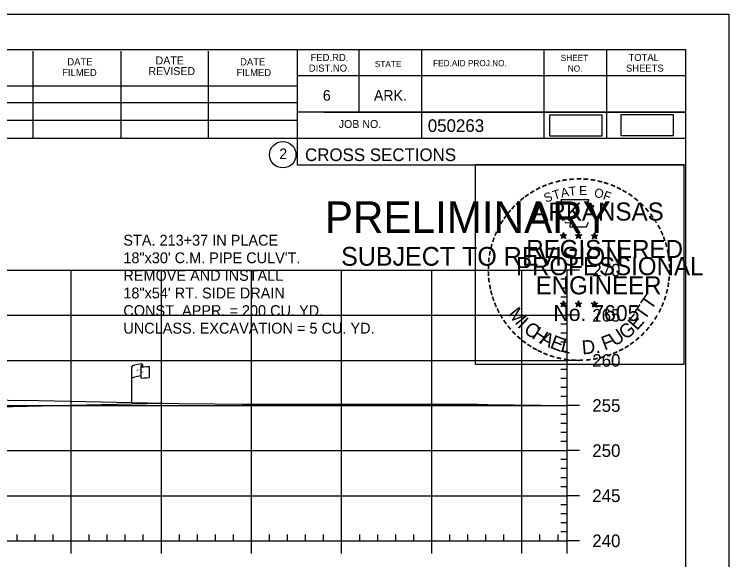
# Model space of a CAD drawing. Extents: x 1365647 to 1367999, y 387113 to 400173.
# Drawn here: x 1365977.8 to 1366057, y 390725.7 to 390786.1 of the extents above; entities that cross this region are included whole.
import ezdxf

# ---------------------------------------------------------------- set-up
doc = ezdxf.new("R2010")
doc.units = 0
for name, color, linetype in [('E_Existing ROW', 7, 'Continuous'), ('R_Axis', 7, 'Continuous'), ('R_Axis Annot', 7, 'Continuous'), ('R_Border', 7, 'Continuous'), ('R_Border PE', 7, 'Continuous'), ('R_Border Prem', 7, 'Continuous'), ('R_Detour', 7, 'Continuous'), ('R_Draft', 7, 'Continuous'), ('R_Drive', 7, 'Continuous'), ('R_Exist Surface', 7, 'Continuous'), ('R_Grid', 7, 'Continuous'), ('R_No Plot', 7, 'Continuous')]:
    doc.layers.add(name, color=color, linetype=linetype)

msp = doc.modelspace()

# ---------------------------------------------------------------- linework, layer by layer
at = {"layer": 'E_Existing ROW'}
for p, q in [((1365991.992, 390747.314), (1365991.992, 390747.074)), ((1365990.829, 390743.113), (1365990.829, 390747.064)), ((1365991.824, 390747.158), (1365991.824, 390747.145)), ((1365991.824, 390747.145), (1365991.824, 390745.918)), ((1365992.76, 390747.121), (1365992.76, 390745.881))]:
    msp.add_line(p, q, dxfattribs=at)
for centre, radius, start, end in [((1365991.902, 390747.159), 0.078, 88.6458, 274.28284), ((1365991.914, 390747.314), 0.0783, 263.07118, 93.95638), ((1365991.903, 390745.918), 0.0783, 180, 273.95638)]:
    msp.add_arc(centre, radius, start, end, dxfattribs=at)
for centre, major_axis, ratio, start_param, end_param in [((1365992.411, 390747.107), (-1.582, -0.043), 0.19887, 5.030368, 6.283185), ((1365993.118, 390747.223), (-1.227, -0.134), 0.052933, 0.159456, 1.268315), ((1365992.406, 390745.789), (-1.582, -0.043), 0.19887, 5.083035, 6.194897), ((1365993.118, 390745.982), (-1.227, -0.134), 0.052933, 0.159456, 1.268315)]:
    msp.add_ellipse(centre, major_axis=major_axis, ratio=ratio, start_param=start_param, end_param=end_param, dxfattribs=at)
at = {"layer": 'R_Axis'}
for p, q in [((1366039.095, 390727.787), (1366039.095, 390757.787)), ((1366040.495, 390757.787), (1366039.095, 390757.787)), ((1366039.095, 390756.787), (1366038.395, 390756.787)), ((1366039.095, 390755.787), (1366038.395, 390755.787)), ((1366039.095, 390754.787), (1366038.395, 390754.787)), ((1366039.095, 390753.787), (1366038.395, 390753.787)), ((1366040.495, 390752.787), (1366039.095, 390752.787)), ((1366039.095, 390751.787), (1366038.395, 390751.787)), ((1366039.095, 390750.787), (1366038.395, 390750.787)), ((1366039.095, 390749.787), (1366038.395, 390749.787)), ((1366039.095, 390748.787), (1366038.395, 390748.787)), ((1366040.495, 390747.787), (1366039.095, 390747.787)), ((1366039.095, 390746.787), (1366038.395, 390746.787)), ((1366039.095, 390745.787), (1366038.395, 390745.787)), ((1366039.095, 390744.787), (1366038.395, 390744.787)), ((1366039.095, 390743.787), (1366038.395, 390743.787)), ((1366040.495, 390742.787), (1366039.095, 390742.787)), ((1366039.095, 390741.787), (1366038.395, 390741.787)), ((1366039.095, 390740.787), (1366038.395, 390740.787)), ((1366039.095, 390739.787), (1366038.395, 390739.787)), ((1366039.095, 390738.787), (1366038.395, 390738.787)), ((1366040.495, 390737.787), (1366039.095, 390737.787)), ((1366039.095, 390736.787), (1366038.395, 390736.787)), ((1366039.095, 390735.787), (1366038.395, 390735.787)), ((1366039.095, 390734.787), (1366038.395, 390734.787)), ((1366039.095, 390733.787), (1366038.395, 390733.787)), ((1366040.495, 390732.787), (1366039.095, 390732.787)), ((1366039.095, 390731.787), (1366038.395, 390731.787)), ((1366039.095, 390730.787), (1366038.395, 390730.787)), ((1366039.095, 390729.787), (1366038.395, 390729.787)), ((1365978.095, 390727.787), (1365978.095, 390728.487)), ((1365980.095, 390727.787), (1365980.095, 390728.487)), ((1365982.095, 390727.787), (1365982.095, 390728.487)), ((1365986.095, 390727.787), (1365986.095, 390728.487)), ((1365988.095, 390727.787), (1365988.095, 390728.487)), ((1365990.095, 390727.787), (1365990.095, 390728.487)), ((1365992.095, 390727.787), (1365992.095, 390728.487)), ((1365996.095, 390727.787), (1365996.095, 390728.487)), ((1365998.095, 390727.787), (1365998.095, 390728.487)), ((1366000.095, 390727.787), (1366000.095, 390728.487)), ((1366002.095, 390727.787), (1366002.095, 390728.487)), ((1366006.095, 390727.787), (1366006.095, 390728.487)), ((1366008.095, 390727.787), (1366008.095, 390728.487)), ((1366010.095, 390727.787), (1366010.095, 390728.487)), ((1366012.095, 390727.787), (1366012.095, 390728.487)), ((1366016.095, 390727.787), (1366016.095, 390728.487)), ((1366018.095, 390727.787), (1366018.095, 390728.487)), ((1366020.095, 390727.787), (1366020.095, 390728.487)), ((1366022.095, 390727.787), (1366022.095, 390728.487)), ((1366026.095, 390727.787), (1366026.095, 390728.487)), ((1366028.095, 390727.787), (1366028.095, 390728.487)), ((1366030.095, 390727.787), (1366030.095, 390728.487)), ((1366032.095, 390727.787), (1366032.095, 390728.487)), ((1366036.095, 390727.787), (1366036.095, 390728.487)), ((1366038.095, 390727.787), (1366038.095, 390728.487)), ((1366039.095, 390728.787), (1366038.395, 390728.787)), ((1365749.095, 390727.787), (1366039.095, 390727.787)), ((1365984.095, 390726.387), (1365984.095, 390727.787)), ((1365994.095, 390726.387), (1365994.095, 390727.787)), ((1366004.095, 390726.387), (1366004.095, 390727.787)), ((1366014.095, 390726.387), (1366014.095, 390727.787)), ((1366024.095, 390726.387), (1366024.095, 390727.787)), ((1366034.095, 390726.387), (1366034.095, 390727.787)), ((1366039.095, 390726.387), (1366039.095, 390727.787)), ((1366040.495, 390727.787), (1366039.095, 390727.787))]:
    msp.add_line(p, q, dxfattribs=at)
at = {"layer": 'R_Border'}
for p, q in [((1365736.095, 390782.247), (1366052.275, 390782.247)), ((1366009.175, 390782.247), (1366009.175, 390769.447)), ((1366016.015, 390782.247), (1366016.015, 390775.307)), ((1366022.955, 390782.247), (1366022.955, 390772.367)), ((1366036.535, 390782.247), (1366036.535, 390772.367)), ((1366043.475, 390782.247), (1366043.475, 390772.367)), ((1366052.275, 390576.787), (1366052.275, 390782.247)), ((1365979.875, 390772.367), (1365979.875, 390782.047)), ((1365989.635, 390772.367), (1365989.635, 390782.047)), ((1365999.315, 390772.367), (1365999.315, 390782.047)), ((1366052.275, 390779.307), (1366009.175, 390779.307)), ((1366052.275, 390779.327), (1366052.275, 390779.327)), ((1365970.015, 390778.227), (1366009.175, 390778.227)), ((1365970.015, 390776.367), (1366009.175, 390776.367)), ((1366052.275, 390775.307), (1366009.175, 390775.307)), ((1366012.135, 390775.307), (1366052.275, 390775.307)), ((1365970.015, 390774.427), (1366009.175, 390774.427)), ((1366052.275, 390772.367), (1365970.015, 390772.367)), ((1366009.175, 390769.447), (1366052.275, 390769.447))]:
    msp.add_line(p, q, dxfattribs=at)
msp.add_circle((1366007.562, 390770.582), 1.467, dxfattribs=at)
at = {"layer": 'R_Border PE'}
for p, q in [((1366038.356, 390761.693), (1366038.705, 390761.582)), ((1366038.356, 390761.693), (1366038.609, 390761.648)), ((1366038.356, 390761.693), (1366038.593, 390761.571)), ((1366038.489, 390761.285), (1366038.705, 390761.582)), ((1366038.489, 390761.285), (1366038.615, 390761.529)), ((1366038.489, 390761.285), (1366038.703, 390761.502)), ((1366038.705, 390761.947), (1366038.664, 390761.695)), ((1366038.918, 390761.285), (1366038.703, 390761.499)), ((1366038.705, 390761.582), (1366038.705, 390761.947)), ((1366038.705, 390761.947), (1366038.754, 390761.697)), ((1366039.052, 390761.693), (1366038.705, 390761.582)), ((1366038.918, 390761.285), (1366038.705, 390761.582)), ((1366039.052, 390761.693), (1366038.766, 390761.644)), ((1366038.918, 390761.285), (1366038.781, 390761.576)), ((1366039.052, 390761.693), (1366038.848, 390761.591)), ((1366040.026, 390761.693), (1366040.375, 390761.582)), ((1366040.026, 390761.693), (1366040.279, 390761.648)), ((1366040.026, 390761.693), (1366040.263, 390761.571)), ((1366040.159, 390761.285), (1366040.375, 390761.582)), ((1366040.159, 390761.285), (1366040.285, 390761.529)), ((1366040.159, 390761.285), (1366040.373, 390761.502)), ((1366040.375, 390761.947), (1366040.334, 390761.695)), ((1366040.588, 390761.285), (1366040.373, 390761.499)), ((1366040.375, 390761.582), (1366040.375, 390761.947)), ((1366040.375, 390761.947), (1366040.424, 390761.697)), ((1366040.722, 390761.693), (1366040.375, 390761.582)), ((1366040.588, 390761.285), (1366040.375, 390761.582)), ((1366040.722, 390761.693), (1366040.436, 390761.644)), ((1366040.588, 390761.285), (1366040.451, 390761.576)), ((1366040.722, 390761.693), (1366040.518, 390761.591)), ((1366041.79, 390761.681), (1366042.139, 390761.57)), ((1366041.79, 390761.681), (1366042.043, 390761.636)), ((1366041.79, 390761.681), (1366042.027, 390761.559)), ((1366041.923, 390761.273), (1366042.139, 390761.57)), ((1366041.923, 390761.273), (1366042.049, 390761.517)), ((1366041.923, 390761.273), (1366042.137, 390761.49)), ((1366042.139, 390761.935), (1366042.098, 390761.683)), ((1366042.352, 390761.273), (1366042.137, 390761.487)), ((1366042.139, 390761.57), (1366042.139, 390761.935)), ((1366042.139, 390761.935), (1366042.188, 390761.685)), ((1366042.486, 390761.681), (1366042.139, 390761.57)), ((1366042.352, 390761.273), (1366042.139, 390761.57)), ((1366042.486, 390761.681), (1366042.2, 390761.632)), ((1366042.352, 390761.273), (1366042.215, 390761.564)), ((1366042.486, 390761.681), (1366042.282, 390761.579)), ((1366038.701, 390754.374), (1366038.66, 390754.122)), ((1366038.701, 390754.009), (1366038.701, 390754.374)), ((1366038.701, 390754.374), (1366038.75, 390754.124)), ((1366040.37, 390754.374), (1366040.329, 390754.122)), ((1366040.37, 390754.009), (1366040.37, 390754.374)), ((1366040.37, 390754.374), (1366040.419, 390754.124)), ((1366042.137, 390754.364), (1366042.096, 390754.112)), ((1366042.137, 390753.999), (1366042.137, 390754.364)), ((1366042.137, 390754.364), (1366042.186, 390754.114)), ((1366038.352, 390754.12), (1366038.701, 390754.009)), ((1366038.352, 390754.12), (1366038.605, 390754.075)), ((1366038.352, 390754.12), (1366038.589, 390753.998)), ((1366038.485, 390753.712), (1366038.701, 390754.009)), ((1366038.485, 390753.712), (1366038.611, 390753.956)), ((1366038.485, 390753.712), (1366038.699, 390753.929)), ((1366038.914, 390753.712), (1366038.699, 390753.926)), ((1366039.048, 390754.12), (1366038.701, 390754.009)), ((1366038.914, 390753.712), (1366038.701, 390754.009)), ((1366039.048, 390754.12), (1366038.762, 390754.071)), ((1366038.914, 390753.712), (1366038.777, 390754.003)), ((1366039.048, 390754.12), (1366038.844, 390754.018)), ((1366040.021, 390754.12), (1366040.37, 390754.009)), ((1366040.021, 390754.12), (1366040.274, 390754.075)), ((1366040.021, 390754.12), (1366040.258, 390753.998)), ((1366040.154, 390753.712), (1366040.37, 390754.009)), ((1366040.154, 390753.712), (1366040.28, 390753.956)), ((1366040.154, 390753.712), (1366040.368, 390753.929)), ((1366040.583, 390753.712), (1366040.368, 390753.926)), ((1366040.717, 390754.12), (1366040.37, 390754.009)), ((1366040.583, 390753.712), (1366040.37, 390754.009)), ((1366040.717, 390754.12), (1366040.431, 390754.071)), ((1366040.583, 390753.712), (1366040.446, 390754.003)), ((1366040.717, 390754.12), (1366040.513, 390754.018)), ((1366041.788, 390754.11), (1366042.137, 390753.999)), ((1366041.788, 390754.11), (1366042.041, 390754.065)), ((1366041.788, 390754.11), (1366042.025, 390753.988)), ((1366041.921, 390753.702), (1366042.137, 390753.999)), ((1366041.921, 390753.702), (1366042.047, 390753.946)), ((1366041.921, 390753.702), (1366042.135, 390753.919)), ((1366042.35, 390753.702), (1366042.135, 390753.916)), ((1366042.484, 390754.11), (1366042.137, 390753.999)), ((1366042.35, 390753.702), (1366042.137, 390753.999)), ((1366042.484, 390754.11), (1366042.198, 390754.061)), ((1366042.35, 390753.702), (1366042.213, 390753.993)), ((1366042.484, 390754.11), (1366042.28, 390754.008))]:
    msp.add_line(p, q, dxfattribs=at)
for points in [[(1366038.397, 390765.571), (1366038.666, 390764.744)], [(1366041.908, 390764.649), (1366042.05, 390764.933), (1366041.365, 390764.909), (1366041.513, 390765.571), (1366038.397, 390765.571)], [(1366038.889, 390763.148), (1366038.889, 390763.061), (1366039.452, 390763.042), (1366039.398, 390762.569), (1366041.268, 390762.569), (1366041.469, 390763.105)], [(1366038.705, 390761.947), (1366038.918, 390761.285), (1366038.356, 390761.693), (1366039.052, 390761.693), (1366038.489, 390761.285), (1366038.705, 390761.947)], [(1366040.375, 390761.947), (1366040.588, 390761.285), (1366040.026, 390761.693), (1366040.722, 390761.693), (1366040.159, 390761.285), (1366040.375, 390761.947)], [(1366042.139, 390761.935), (1366042.352, 390761.273), (1366041.79, 390761.681), (1366042.486, 390761.681), (1366041.923, 390761.273), (1366042.139, 390761.935)], [(1366038.701, 390754.374), (1366038.914, 390753.712), (1366038.352, 390754.12), (1366039.048, 390754.12), (1366038.485, 390753.712), (1366038.701, 390754.374)], [(1366040.37, 390754.374), (1366040.583, 390753.712), (1366040.021, 390754.12), (1366040.717, 390754.12), (1366040.154, 390753.712), (1366040.37, 390754.374)], [(1366042.137, 390754.364), (1366042.35, 390753.702), (1366041.788, 390754.11), (1366042.484, 390754.11), (1366041.921, 390753.702), (1366042.137, 390754.364)]]:
    msp.add_lwpolyline(points, dxfattribs=at)
for centre, radius in [((1366038.704, 390761.582), 0.172), ((1366038.704, 390761.582), 0.145), ((1366038.704, 390761.582), 0.116), ((1366038.704, 390761.582), 0.0991), ((1366038.704, 390761.582), 0.0747), ((1366038.704, 390761.582), 0.0495), ((1366038.704, 390761.582), 0.0296), ((1366040.374, 390761.582), 0.172), ((1366040.374, 390761.582), 0.145), ((1366040.374, 390761.582), 0.116), ((1366040.374, 390761.582), 0.0991), ((1366040.374, 390761.582), 0.0747), ((1366040.374, 390761.582), 0.0495), ((1366040.374, 390761.582), 0.0296), ((1366042.138, 390761.57), 0.172), ((1366042.138, 390761.57), 0.145), ((1366042.138, 390761.57), 0.116), ((1366042.138, 390761.57), 0.0991), ((1366042.138, 390761.57), 0.0747), ((1366042.138, 390761.57), 0.0495), ((1366042.138, 390761.57), 0.0296), ((1366038.7, 390754.009), 0.172), ((1366038.7, 390754.009), 0.145), ((1366038.7, 390754.009), 0.116), ((1366038.7, 390754.009), 0.0991), ((1366038.7, 390754.009), 0.0747), ((1366038.7, 390754.009), 0.0495), ((1366038.7, 390754.009), 0.0296), ((1366040.369, 390754.009), 0.172), ((1366040.369, 390754.009), 0.145), ((1366040.369, 390754.009), 0.116), ((1366040.369, 390754.009), 0.0991), ((1366040.369, 390754.009), 0.0747), ((1366040.369, 390754.009), 0.0495), ((1366040.369, 390754.009), 0.0296), ((1366042.136, 390753.999), 0.172), ((1366042.136, 390753.999), 0.145), ((1366042.136, 390753.999), 0.116), ((1366042.136, 390753.999), 0.0991), ((1366042.136, 390753.999), 0.0747), ((1366042.136, 390753.999), 0.0495), ((1366042.136, 390753.999), 0.0296)]:
    msp.add_circle(centre, radius, dxfattribs=at)
at = {"layer": 'R_Detour'}
for points in [[(1366037.165, 390772.664), (1366042.998, 390772.664), (1366042.998, 390774.974), (1366037.165, 390774.974)], [(1366045.079, 390772.695), (1366050.912, 390772.695), (1366050.912, 390775.005), (1366045.079, 390775.005)]]:
    msp.add_lwpolyline(points, close=True, dxfattribs=at)
at = {"layer": 'R_Drive'}
msp.add_line((1365938.586, 390741.803), (1365994.095, 390743.044), dxfattribs=at)
at = {"layer": 'R_Exist Surface'}
msp.add_lwpolyline([(1365973.682, 390743.429), (1365980.489, 390743.33), (1365996.043, 390743.003), (1365999.982, 390742.955), (1366003.112, 390742.917), (1366014.733, 390742.933), (1366026.682, 390742.949), (1366029.003, 390742.923), (1366029.162, 390742.925), (1366030.306, 390742.904), (1366039.095, 390742.773)], dxfattribs=at)
at = {"layer": 'R_Grid'}
for p, q in [((1365749.095, 390757.787), (1366039.095, 390757.787)), ((1365984.095, 390727.787), (1365984.095, 390757.787)), ((1365994.095, 390727.787), (1365994.095, 390757.787)), ((1366004.095, 390727.787), (1366004.095, 390757.787)), ((1366014.095, 390727.787), (1366014.095, 390757.787)), ((1366024.095, 390727.787), (1366024.095, 390757.787)), ((1366034.095, 390727.787), (1366034.095, 390757.787)), ((1366039.095, 390727.787), (1366039.095, 390757.787)), ((1365749.095, 390752.787), (1366039.095, 390752.787)), ((1365749.095, 390747.787), (1366039.095, 390747.787)), ((1365749.095, 390742.787), (1366039.095, 390742.787)), ((1365749.095, 390737.787), (1366039.095, 390737.787)), ((1365749.095, 390732.787), (1366039.095, 390732.787)), ((1365749.095, 390727.787), (1366039.095, 390727.787))]:
    msp.add_line(p, q, dxfattribs=at)
at = {"layer": 'R_No Plot'}
msp.add_line((1365723.694, 390786.141), (1366057.027, 390786.141), dxfattribs=at)
for points in [[(1365723.687, 390786.141), (1366057.027, 390786.141), (1366057.027, 390572.804), (1365723.687, 390572.804)], [(1366028.946, 390769.479), (1366052.044, 390769.479), (1366052.044, 390747.329), (1366028.946, 390747.329)]]:
    msp.add_lwpolyline(points, close=True, dxfattribs=at)

# ---------------------------------------------------------------- texts
at = {"layer": 'E_Existing ROW'}
for s, height, rotation, p in [('R ', 0.2, 9.98841, (1365991.348, 390746.565)), (' O', 0.2, 9.98841, (1365991.494, 390746.61)), ('W', 0.2, 351.17882, (1365991.824, 390746.441)), ('DWB 11-9-07', 0.001, 90, (1365991.992, 390747.074)), ('DWB 11-9-07', 0.001, 5.07169, (1365992.749, 390745.88)), ('DWB 11-9-07', 0.001, 90, (1365990.828, 390743.113))]:
    msp.add_text(s, height=height, rotation=rotation, dxfattribs=at).set_placement(p)
at = {"layer": 'R_Axis Annot'}
for s, p in [('270', (1366041.895, 390757.087)), ('265', (1366041.895, 390752.087)), ('260', (1366041.895, 390747.087)), ('255', (1366041.895, 390742.087)), ('250', (1366041.895, 390737.087)), ('245', (1366041.895, 390732.087)), ('240', (1366041.895, 390727.087))]:
    msp.add_text(s, height=1.4, dxfattribs=at).set_placement(p)
at = {"layer": 'R_Border'}
for s, height, p in [('DATE', 0.7819, (1365983.675, 390780.487)), ('DATE', 0.8792, (1365993.455, 390780.587)), ('DATE', 0.7819, (1366002.835, 390780.487)), ('FED.RD.', 0.7819, (1366010.655, 390780.967)), ('SHEET', 0.684, (1366038.395, 390780.967)), ('TOTAL', 0.7819, (1366045.915, 390780.967)), ('DIST.NO.', 0.7819, (1366010.455, 390779.787)), ('STATE', 0.684, (1366017.775, 390780.287)), ('FED.AID PROJ.NO.', 0.684, (1366024.235, 390780.387)), ('NO.', 0.684, (1366039.175, 390779.787)), ('SHEETS', 0.7819, (1366045.635, 390779.787)), ('FILMED', 0.7819, (1365983.095, 390779.307)), ('REVISED', 0.8792, (1365992.675, 390779.407)), ('FILMED', 0.7819, (1366002.435, 390779.307)), ('6', 1.172, (1366012.015, 390776.567)), ('ARK.', 1.1723, (1366017.675, 390776.567)), ('JOB NO.', 0.8792, (1366013.775, 390773.547)), ('050263', 1.4, (1366023.651, 390773.106)), ('2', 1.172, (1366007.179, 390770.096)), ('CROSS SECTIONS', 1.4, (1366010.038, 390769.877))]:
    msp.add_text(s, height=height, rotation=360, dxfattribs=at).set_placement(p)
at = {"layer": 'R_Border PE'}
for s, height, rotation, p in [('-', 1.6, 10.21935, (1366038.573, 390767.101)), ('-', 1.6, 5.89682, (1366039.302, 390767.211)), ('-', 1.6, 0.18623, (1366040.074, 390767.283)), ('-', 1.6, 357.74304, (1366040.797, 390767.27)), ('-', 1.6, 352.16172, (1366041.541, 390767.214)), ('-', 1.6, 28.79182, (1366035.878, 390766.112)), ('-', 1.6, 24.30721, (1366036.511, 390766.429)), ('-', 1.6, 19.17608, (1366037.145, 390766.698)), ('-', 1.6, 13.63015, (1366037.895, 390766.939)), ('T', 1, 6.02276, (1366039.341, 390765.997)), ('E', 1, 0.83234, (1366040.446, 390766.107)), ('-', 1.6, 347.20489, (1366042.26, 390767.1)), ('-', 1.6, 342.3362, (1366042.895, 390766.945)), ('-', 1.6, 337.85509, (1366043.63, 390766.722)), ('-', 1.6, 334.12109, (1366044.261, 390766.451)), ('-', 1.6, 36.23174, (1366034.703, 390765.347)), ('-', 1.6, 34.06357, (1366035.281, 390765.742)), ('S', 1, 21.59401, (1366036.752, 390765.249)), ('T', 1, 16.4036, (1366037.666, 390765.58)), ('A', 1, 11.21318, (1366038.492, 390765.831)), ('O', 1, 350.4515, (1366042.05, 390765.897)), ('F', 1, 340.07066, (1366043.004, 390765.669)), ('-', 1.6, 329.64089, (1366044.84, 390766.168)), ('-', 1.6, 325.86266, (1366045.483, 390765.807)), ('-', 1.6, 42.96224, (1366033.794, 390764.552)), ('-', 1.6, 38.95066, (1366034.227, 390764.969)), ('-', 1.6, 320.52971, (1366046.093, 390765.381)), ('-', 1.6, 48.42305, (1366033.346, 390764.074)), ('ARKANSAS', 2, 360, (1366035.25, 390763.283)), ('-', 1.6, 315.57859, (1366046.692, 390764.893)), ('-', 1.6, 309.87973, (1366047.261, 390764.343)), ('-', 1.6, 54.23247, (1366032.53, 390763.021)), ('-', 1.6, 50.61417, (1366032.943, 390763.588)), ('-', 1.6, 306.65218, (1366047.786, 390763.741)), ('-', 1.6, 58.07063, (1366032.205, 390762.494)), ('-', 1.4, 303.67529, (1366048.272, 390763.173)), ('-', 1.6, 62.87135, (1366031.892, 390761.88)), ('-', 1.6, 299.66835, (1366048.591, 390762.566)), ('-', 1.6, 67.77427, (1366031.633, 390761.269)), ('DWB', 0.01, 360, (1366038.691, 390761.577)), ('DWB', 0.01, 360, (1366040.361, 390761.577)), ('DWB', 0.01, 360, (1366042.125, 390761.565)), ('-', 1.6, 294.66279, (1366048.915, 390761.954)), ('-', 1.6, 290.57283, (1366049.172, 390761.377)), ('-', 1.6, 75.46096, (1366031.217, 390759.925)), ('-', 1.6, 72.39447, (1366031.414, 390760.639)), ('REGISTERED', 2, 360, (1366034.572, 390759.134)), ('-', 1.6, 285.12326, (1366049.406, 390760.797)), ('-', 1.6, 81.20126, (1366031.085, 390759.212)), ('-', 1.6, 280.54934, (1366049.606, 390760.055)), ('-', 1.6, 85.18634, (1366031.009, 390758.521)), ('PROFESSIONAL', 2, 360, (1366033.424, 390757.23)), ('-', 1.6, 276.59616, (1366049.768, 390759.287)), ('-', 1.6, 89.06224, (1366030.984, 390757.82)), ('-', 1.6, 274.33011, (1366049.828, 390758.565)), ('-', 1.6, 94.19588, (1366031.019, 390757.095)), ('-', 1.6, 269.94067, (1366049.862, 390757.933)), ('-', 1.6, 98.94793, (1366031.091, 390756.428)), ('ENGINEER', 2, 360, (1366035.611, 390755.105)), ('-', 1.6, 263.5172, (1366049.843, 390757.267)), ('-', 1.6, 101.71495, (1366031.226, 390755.695)), ('-', 1.6, 260.99529, (1366049.772, 390756.613)), ('-', 1.6, 105.45785, (1366031.388, 390755.1)), ('T', 1.54, 55.05496, (1366048.42, 390753.274)), ('-', 1.6, 255.7626, (1366049.662, 390755.935)), ('-', 1.6, 109.08742, (1366031.603, 390754.469)), ('-', 1.6, 252.86809, (1366049.481, 390755.215)), ('-', 1.6, 114.06432, (1366031.857, 390753.873)), ('-', 1.6, 115.72885, (1366032.162, 390753.255)), ('M', 1.54, 308.91747, (1366032.472, 390752.9)), ('No. 7605', 1.757, 360, (1366037.585, 390752.154)), ('DWB', 0.01, 360, (1366038.686, 390754.005)), ('DWB', 0.01, 360, (1366040.355, 390754.003)), ('DWB', 0.01, 360, (1366042.122, 390753.994)), ('T', 1.54, 55.05496, (1366047.689, 390752.154)), ('-', 1.6, 244.61971, (1366048.996, 390753.913)), ('-', 1.6, 247.88866, (1366049.258, 390754.542)), ('-', 1.6, 120.44712, (1366032.519, 390752.669)), ('E', 1.54, 48.73133, (1366046.843, 390751.027)), ('-', 1.6, 239.07125, (1366048.602, 390753.161)), ('-', 1.6, 125.89344, (1366032.922, 390752.108)), ('I', 1.54, 316.46364, (1366033.514, 390751.58)), ('C', 1.54, 324.01974, (1366034.187, 390750.957)), ('-', 1.6, 233.84524, (1366048.2, 390752.508)), ('-', 1.6, 130.71812, (1366033.384, 390751.556)), ('H', 1.54, 327.53419, (1366035.097, 390750.302)), ('U', 1.54, 34.40523, (1366044.391, 390749.274)), ('G', 1.54, 38.21734, (1366045.59, 390750.007)), ('-', 1.6, 231.25377, (1366047.77, 390751.942)), ('-', 1.6, 134.22381, (1366033.901, 390751.011)), ('-', 1.6, 138.93382, (1366034.426, 390750.547)), ('A', 1.54, 332.55127, (1366035.951, 390749.765)), ('E', 1.54, 339.20679, (1366037.109, 390749.203)), ('F', 1.54, 20.82016, (1366043.254, 390748.88)), ('-', 1.6, 221.08509, (1366046.769, 390750.869)), ('-', 1.6, 225.76533, (1366047.291, 390751.378)), ('-', 1.6, 144.64634, (1366034.982, 390750.141)), ('-', 1.6, 148.08978, (1366035.543, 390749.77)), ('L', 1.54, 346.2929, (1366038.301, 390748.779)), ('D.', 1.54, 5.26016, (1366040.804, 390748.442)), ('-', 1.6, 215.73633, (1366046.22, 390750.397)), ('-', 1.6, 151.57039, (1366036.122, 390749.445)), ('-', 1.6, 154.60019, (1366036.644, 390749.198)), ('-', 1.6, 204.25161, (1366044.504, 390749.345)), ('-', 1.6, 207.35684, (1366045.128, 390749.664)), ('-', 1.6, 212.24909, (1366045.686, 390750.01)), ('-', 1.6, 158.56121, (1366037.268, 390748.944)), ('-', 1.6, 162.79826, (1366037.955, 390748.731)), ('-', 1.6, 167.55551, (1366038.67, 390748.567)), ('-', 1.6, 173.11546, (1366039.442, 390748.457)), ('-', 1.6, 191.28576, (1366042.479, 390748.631)), ('-', 1.6, 195.47429, (1366043.208, 390748.83)), ('-', 1.6, 200.71842, (1366043.885, 390749.072)), ('-', 1.6, 176.51827, (1366040.19, 390748.404)), ('-', 1.6, 181.59176, (1366040.934, 390748.423)), ('-', 1.6, 185.81666, (1366041.743, 390748.499))]:
    msp.add_text(s, height=height, rotation=rotation, dxfattribs=at).set_placement(p)
at = {"layer": 'R_Border Prem'}
for s, height, p in [('PRELIMINARY', 3.5, (1366012.226, 390761.91)), ('DWB', 0.01, (1366012.973, 390763.759)), ('SUBJECT TO REVISION', 2.07511, (1366014.035, 390758.281))]:
    msp.add_text(s, height=height, rotation=360, dxfattribs=at).set_placement(p)
at = {"layer": 'R_Draft'}
for s, p in [('STA. 213+37 IN PLACE', (1365989.882, 390760.505)), ('18"x30\' C.M. PIPE CULV\'T.', (1365989.882, 390758.555)), ('REMOVE AND INSTALL ', (1365989.882, 390756.605)), ('18"x54\' RT. SIDE DRAIN', (1365989.882, 390754.655)), ('CONST. APPR. = 200 CU. YD.', (1365989.882, 390752.705)), ('UNCLASS. EXCAVATION = 5 CU. YD. ', (1365989.882, 390750.755))]:
    msp.add_text(s, height=1.2, rotation=360, dxfattribs=at).set_placement(p)

doc.saveas('drawing.dxf')
